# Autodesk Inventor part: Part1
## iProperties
Shininess: 65.0
Angle Display Precision: 2
Document Length Units: 11269
Document Angle Units: 11283
Document Time Units: 11279
Document Mass Units: 11290
Document Length Units Precision: 3
Document Angle Units Precision: 2
Compacted: False
PropertySet Name: _Private Model Information
Created: 2002-04
Part Number: Part1
Material: Stainless Steel, 440C
Document SubType Name: Sheet Metal
Control State: 0
Master: False
Checked Out: False
PropertySet Name: Design Tracking Control
Density: 0.0
Volumn: 0.0
Area: 0.0
PropertySet Name: Model Information
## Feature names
1. Corner1
2. Hole1
3. Corner Chamfer1
4. Corner Round1
5. Plate1
6. Plate2
7. Bend1
8. Plate3
9. Bend2
10. Cut1
